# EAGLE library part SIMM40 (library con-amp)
AMP connector
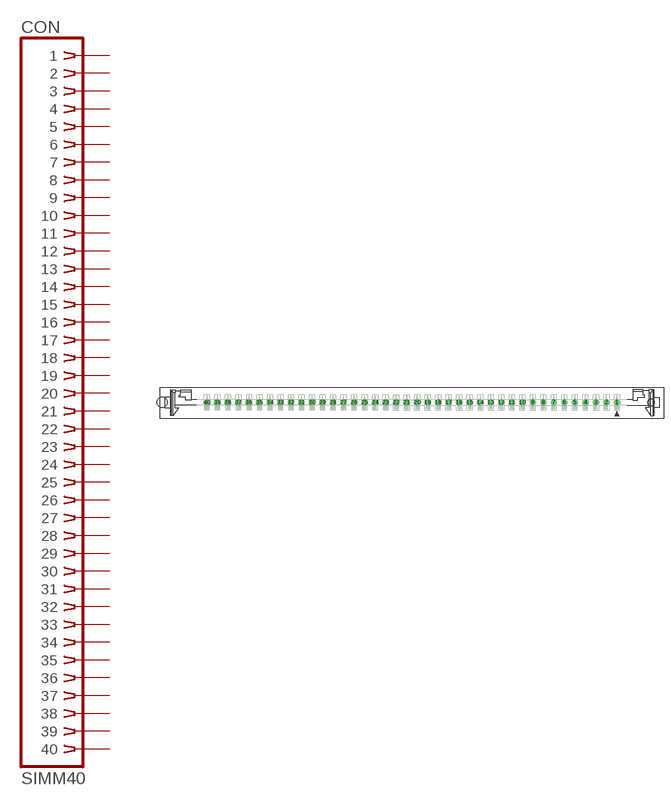
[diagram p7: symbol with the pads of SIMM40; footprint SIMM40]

Designator prefix CON

## SIMM40 (OC_FARNELL: unknown; OC_NEWARK: unknown)  [SIMM40]
1  1  pas
2  2  pas
3  3  pas
4  4  pas
5  5  pas
6  6  pas
7  7  pas
8  8  pas
9  9  pas
10  10  pas
11  11  pas
12  12  pas
13  13  pas
14  14  pas
15  15  pas
16  16  pas
17  17  pas
18  18  pas
19  19  pas
20  20  pas
21  21  pas
22  22  pas
23  23  pas
24  24  pas
25  25  pas
26  26  pas
27  27  pas
28  28  pas
29  29  pas
30  30  pas
31  31  pas
32  32  pas
33  33  pas
34  34  pas
35  35  pas
36  36  pas
37  37  pas
38  38  pas
39  39  pas
40  40  pas

## Footprint SIMM40 (pad centres in mm)
SIMM connector
drill 1.016 octagon: 1 49.53,0; 2 46.99,0; 3 44.45,0; 4 41.91,0; 5 39.37,0; 6 36.83,0; 7 34.29,0; 8 31.75,0; 9 29.21,0; 10 26.67,0; 11 24.13,0; 12 21.59,0; 13 19.05,0; 14 16.51,0; 15 13.97,0; 16 11.43,0; 17 8.89,0; 18 6.35,0; 19 3.81,0; 20 1.27,0; 21 -1.27,0; 22 -3.81,0; 23 -6.35,0; 24 -8.89,0; 25 -11.43,0; 26 -13.97,0; 27 -16.51,0; 28 -19.05,0; 29 -21.59,0; 30 -24.13,0; 31 -26.67,0; 32 -29.21,0; 33 -31.75,0; 34 -34.29,0; 35 -36.83,0; 36 -39.37,0; 37 -41.91,0; 38 -44.45,0; 39 -46.99,0; 40 -49.53,0
hole 2.413 at -60.35,0.025
hole 1.6 at 57.785,0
